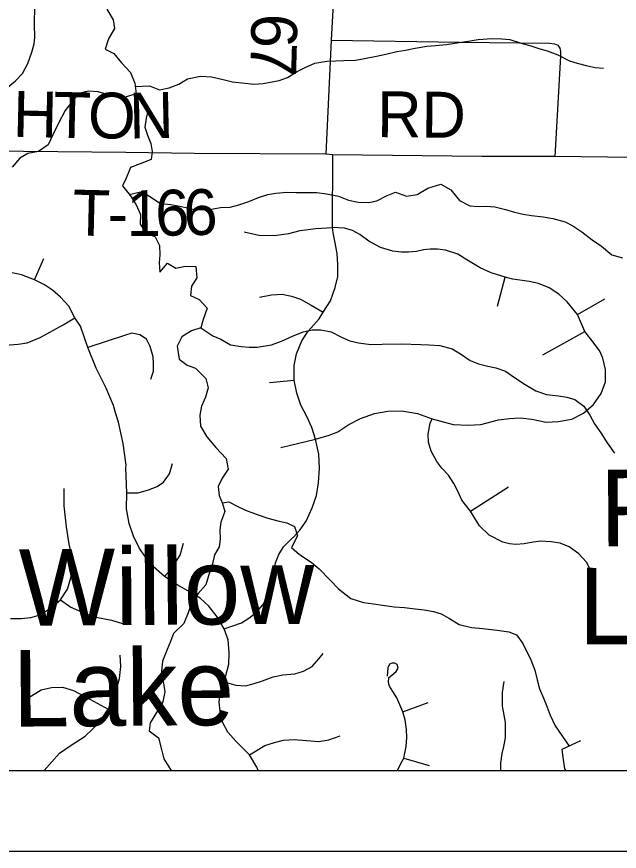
# Model space of a CAD drawing. Extents: x 0 to 34, y 0 to 22.
# Drawn here: x 3.245 to 3.992, y 14 to 15.034 of the extents above; entities that cross this region are included whole.
import ezdxf

# ---------------------------------------------------------------- set-up
doc = ezdxf.new("R2010")
doc.units = 0
for name, color, linetype in [('GM_X_County_Text', 7, 'Continuous'), ('GM_X_Minor_Lake', 7, 'Continuous'), ('GM_X_Minor_Lake_Text', 7, 'Continuous'), ('GM_X_Minor_River', 7, 'Continuous'), ('GM_X_Township_Road', 7, 'Continuous'), ('GM_X_Township_Road_Text', 7, 'Continuous'), ('SH_Cut_Line', 7, 'Continuous'), ('SH_Data', 7, 'Continuous')]:
    doc.layers.add(name, color=color, linetype=linetype)

msp = doc.modelspace()

# ---------------------------------------------------------------- linework, layer by layer
at = {"layer": 'GM_X_County_Text'}
msp.add_lwpolyline([(2.1, 15.3556), (2.1, 14.1), (4.3787, 14.1), (4.3725, 14.1373), (4.3676, 14.1533), (4.4185, 14.2906), (4.4707, 14.5032), (4.0058, 14.5086), (4.0092, 14.8604), (4.002, 15.1777), (4.1154, 15.1803), (4.1171, 15.3509), (3.8077, 15.3535), (3.6529, 15.3542), (3.32, 15.3518), (3.0143, 15.3554), (2.8413, 15.3568), (2.5967, 15.3568)], close=True, dxfattribs=at)
at = {"layer": 'GM_X_Minor_Lake'}
for points in [[(3.9435, 14.137), (3.9205, 14.1261)], [(3.9205, 14.1261), (3.9221, 14.1139), (3.9238, 14.1022), (3.9251, 14.1)]]:
    msp.add_lwpolyline(points, dxfattribs=at)
at = {"layer": 'GM_X_Minor_River'}
for points in [[(3.3566, 15.0437), (3.3644, 15.0305), (3.366, 15.0199), (3.3586, 15.0069), (3.3542, 14.9943), (3.3652, 14.9887), (3.3748, 14.9774), (3.3859, 14.9654), (3.391, 14.9522), (3.3927, 14.9389), (3.4022, 14.931), (3.408, 14.9208), (3.4051, 14.9086), (3.4034, 14.8976), (3.4069, 14.8878), (3.4108, 14.8772), (3.4128, 14.8673), (3.4114, 14.8574), (3.3978, 14.8519), (3.3857, 14.8476), (3.3802, 14.8343), (3.3757, 14.8247), (3.3857, 14.8123), (3.3927, 14.8013), (3.3981, 14.7892), (3.3979, 14.7771), (3.4052, 14.7665), (3.4162, 14.7617), (3.4216, 14.7508), (3.4222, 14.7394), (3.4211, 14.7295), (3.422, 14.7177), (3.4314, 14.7288), (3.442, 14.7229), (3.4534, 14.7253), (3.4667, 14.7247), (3.468, 14.7106), (3.4612, 14.7003), (3.4602, 14.6889), (3.4709, 14.6841), (3.4809, 14.6732), (3.4757, 14.659), (3.4728, 14.6487), (3.4615, 14.6452), (3.4494, 14.6375), (3.4435, 14.626), (3.4459, 14.6101), (3.4559, 14.6026), (3.4662, 14.5989), (3.4792, 14.5858), (3.482, 14.5744), (3.4787, 14.5629), (3.4739, 14.5519), (3.4717, 14.5405), (3.4723, 14.5268), (3.4804, 14.5136), (3.4915, 14.5004), (3.5042, 14.4869), (3.5066, 14.4736), (3.4995, 14.4625), (3.4943, 14.4522), (3.4956, 14.4412), (3.4998, 14.431), (3.5026, 14.4211), (3.4978, 14.4078), (3.4964, 14.3983), (3.4969, 14.3869), (3.4955, 14.3773), (3.4899, 14.3674), (3.487, 14.3545), (3.4826, 14.3415), (3.479, 14.3304)], [(3.3915, 14.948), (3.4092, 14.9486), (3.4218, 14.9438), (3.4335, 14.9462), (3.4456, 14.9509), (3.4565, 14.9575), (3.4724, 14.9607), (3.486, 14.9601), (3.5005, 14.9564), (3.5123, 14.9535), (3.5274, 14.9522), (3.5385, 14.9508), (3.5502, 14.9517), (3.5699, 14.9553), (3.5804, 14.9592), (3.5925, 14.9666), (3.6023, 14.9713), (3.6143, 14.9767), (3.6291, 14.9792), (3.6401, 14.9797), (3.6503, 14.9802), (3.6647, 14.9807), (3.6757, 14.9827), (3.6908, 14.9856), (3.7022, 14.988), (3.7158, 14.9912), (3.7264, 14.9928), (3.7385, 14.9956), (3.7528, 14.9981), (3.7638, 14.9989), (3.7774, 14.9998), (3.793, 15.0023), (3.8043, 15.0043), (3.8168, 15.006), (3.8335, 15.0073), (3.846, 15.0071), (3.8558, 15.0061), (3.8699, 15.0017), (3.8817, 14.9984), (3.892, 14.9951), (3.9022, 14.9921), (3.9152, 14.987), (3.9297, 14.9799), (3.9392, 14.977), (3.9506, 14.9741), (3.9616, 14.9715), (3.9718, 14.9705)], [(3.3927, 14.9389), (3.3791, 14.9346), (3.3662, 14.9363), (3.3555, 14.9385), (3.3456, 14.9414), (3.3335, 14.942), (3.3214, 14.9392), (3.3124, 14.9277), (3.3046, 14.9181), (3.296, 14.9017), (3.2894, 14.8879), (3.2838, 14.8757), (3.2718, 14.8672), (3.2586, 14.8648), (3.2488, 14.859), (3.239, 14.8479)], [(3.3842, 14.8142), (3.4001, 14.8178), (3.4096, 14.8114), (3.423, 14.8028), (3.4359, 14.8018), (3.4488, 14.7993), (3.4628, 14.7957), (3.4746, 14.7951), (3.486, 14.7959), (3.4973, 14.798), (3.5094, 14.7985), (3.52, 14.8013), (3.5325, 14.8052), (3.5442, 14.8103), (3.5559, 14.8142), (3.5657, 14.8158), (3.5793, 14.8171), (3.5911, 14.8165), (3.6036, 14.8166), (3.6165, 14.8164), (3.6286, 14.815), (3.6435, 14.8118), (3.656, 14.807), (3.6678, 14.8045), (3.6811, 14.8042), (3.6909, 14.8062), (3.7037, 14.8128), (3.7143, 14.8168), (3.728, 14.812), (3.7412, 14.814), (3.7544, 14.8221), (3.7703, 14.8269), (3.7828, 14.8198), (3.7936, 14.8066), (3.8062, 14.7999), (3.8168, 14.7993), (3.8267, 14.7994), (3.8373, 14.7988), (3.8506, 14.7955), (3.8616, 14.7922), (3.8722, 14.7897), (3.8829, 14.7879), (3.8973, 14.7865), (3.9091, 14.7844), (3.9243, 14.78), (3.9338, 14.7752), (3.9449, 14.7677), (3.9579, 14.758), (3.9693, 14.7501), (3.9823, 14.7392), (3.9956, 14.7356)], [(3.4728, 14.6487), (3.4877, 14.6387), (3.4976, 14.6346), (3.5098, 14.6279), (3.5235, 14.6258), (3.5329, 14.6247), (3.5428, 14.6248), (3.5606, 14.6277), (3.5727, 14.6324), (3.5866, 14.6383), (3.5998, 14.6437), (3.6108, 14.6465), (3.6218, 14.6463), (3.6343, 14.6437), (3.6473, 14.6374), (3.6576, 14.6326), (3.6682, 14.6301), (3.6834, 14.628), (3.6978, 14.6285), (3.7213, 14.6288), (3.7455, 14.6283), (3.7554, 14.6276), (3.769, 14.627), (3.7846, 14.6226), (3.7949, 14.6167), (3.8068, 14.6084), (3.8171, 14.604), (3.8288, 14.6011), (3.8387, 14.5993), (3.8505, 14.5949), (3.8616, 14.5874), (3.8749, 14.5784), (3.8879, 14.5706), (3.9012, 14.5662), (3.916, 14.5645), (3.9267, 14.5627), (3.9366, 14.5598), (3.9476, 14.5519), (3.955, 14.5406), (3.9608, 14.53), (3.9688, 14.5187), (3.9766, 14.5063), (3.9854, 14.4934)], [(3.4994, 14.432), (3.5078, 14.433), (3.5181, 14.4278), (3.5284, 14.4229), (3.5428, 14.4174), (3.5558, 14.413), (3.5698, 14.4093), (3.5793, 14.4072), (3.5888, 14.4027), (3.5928, 14.391), (3.5853, 14.3765), (3.5953, 14.3678), (3.6098, 14.3585), (3.6194, 14.3499), (3.6328, 14.3363), (3.6435, 14.3254), (3.6588, 14.3135), (3.6744, 14.3083), (3.6869, 14.3069), (3.6979, 14.3052), (3.7127, 14.3031), (3.7253, 14.3021), (3.7385, 14.3007), (3.7495, 14.2993), (3.7613, 14.2971), (3.7708, 14.2942), (3.7811, 14.2886), (3.793, 14.2812), (3.8082, 14.2772), (3.8184, 14.2765), (3.8294, 14.2755), (3.84, 14.2741), (3.8548, 14.272), (3.8643, 14.2683), (3.872, 14.2577), (3.8821, 14.2373), (3.8868, 14.2245), (3.8896, 14.2127), (3.8928, 14.2014), (3.8982, 14.1889), (3.9021, 14.1787), (3.906, 14.1688), (3.9122, 14.1556), (3.9292, 14.1302)], [(3.479, 14.3304), (3.4696, 14.3197), (3.4607, 14.3051), (3.4574, 14.2956), (3.4518, 14.2822), (3.4391, 14.2699), (3.4354, 14.26), (3.4313, 14.2501), (3.4254, 14.2356), (3.4241, 14.2227), (3.4257, 14.2132), (3.4281, 14.1976), (3.426, 14.1854), (3.4178, 14.1721), (3.41, 14.1591), (3.409, 14.1495), (3.4204, 14.1406), (3.424, 14.1262), (3.4272, 14.1148), (3.4353, 14.1012), (3.4361, 14.1)]]:
    msp.add_lwpolyline(points, dxfattribs=at)
at = {"layer": 'GM_X_Township_Road'}
for p, q in [((3.2668, 14.7085), (3.2784, 14.7348)), ((3.8404, 14.6757), (3.8499, 14.7114)), ((3.9398, 14.6655), (3.9736, 14.6848)), ((3.8969, 14.6154), (3.9489, 14.6442)), ((3.558, 14.5812), (3.5884, 14.5839)), ((3.572, 14.5004), (3.6149, 14.511)), ((3.8071, 14.4217), (3.8543, 14.4519)), ((3.7233, 14.173), (3.7546, 14.1844)), ((3.7244, 14.1153), (3.7559, 14.1062))]:
    msp.add_line(p, q, dxfattribs=at)
for points in [[(3.653, 15.3536), (3.6423, 15.1486), (3.6346, 15.0053), (3.628, 14.8639)], [(3.0894, 14.9172), (3.0915, 14.924), (3.1008, 14.9208), (3.1119, 14.9183), (3.1215, 14.9176), (3.1332, 14.9172), (3.1543, 14.9169), (3.165, 14.9172), (3.1849, 14.9215), (3.196, 14.9254), (3.2035, 14.9293), (3.2159, 14.9354), (3.2316, 14.9454), (3.2434, 14.955), (3.2519, 14.9639), (3.2584, 14.9764), (3.2633, 14.9903), (3.2662, 15.0006), (3.2673, 15.0088), (3.2669, 15.0252), (3.2673, 15.0473), (3.2673, 15.0719), (3.2673, 15.0858), (3.2675, 15.0945)], [(3.6346, 15.0053), (3.7936, 15.003), (3.905, 15.0018), (3.9114, 15.0009), (3.9153, 14.9991), (3.9178, 14.9956), (3.9187, 14.9915), (3.9187, 14.9857), (3.9115, 14.861)], [(4.0094, 14.8598), (3.9115, 14.861), (3.821, 14.8613), (3.6366, 14.8632), (3.628, 14.8639), (3.4647, 14.8648), (3.38, 14.8663), (3.1683, 14.8681), (3.1666, 14.8681), (3.0076, 14.867), (2.8745, 14.8645)], [(3.5869, 14.3888), (3.5876, 14.3895), (3.5956, 14.3979), (3.6035, 14.4093), (3.6107, 14.4256), (3.6161, 14.4411), (3.6187, 14.4567), (3.6199, 14.4749), (3.6191, 14.4924), (3.6149, 14.511), (3.6104, 14.5254), (3.6047, 14.5379), (3.5967, 14.5531), (3.5918, 14.5679), (3.5884, 14.5839), (3.5887, 14.6021), (3.5914, 14.6165), (3.5982, 14.6328), (3.6058, 14.6446), (3.6195, 14.6598), (3.6244, 14.6681), (3.6335, 14.6822), (3.6396, 14.6989), (3.6426, 14.7125), (3.6426, 14.7273), (3.6419, 14.741), (3.6388, 14.7562), (3.6369, 14.7664), (3.6362, 14.7732), (3.6366, 14.8632)], [(3.5265, 14.7679), (3.5447, 14.7638), (3.5637, 14.7634), (3.5819, 14.7657), (3.5959, 14.7694), (3.6153, 14.7721), (3.6362, 14.7732)], [(3.6149, 14.511), (3.632, 14.5159), (3.6426, 14.5201), (3.6563, 14.5288), (3.6707, 14.5364), (3.6882, 14.5425), (3.7045, 14.5455), (3.7216, 14.5459), (3.7413, 14.5425), (3.7595, 14.536), (3.7855, 14.5289), (3.8042, 14.5282), (3.8201, 14.5289), (3.842, 14.5347), (3.8556, 14.5364), (3.8688, 14.5372), (3.8833, 14.5356), (3.9011, 14.5318), (3.9159, 14.5326), (3.9326, 14.5356), (3.947, 14.5432), (3.9596, 14.5539), (3.969, 14.5675), (3.9744, 14.582), (3.9744, 14.5971), (3.9713, 14.6112), (3.9675, 14.6199), (3.9592, 14.6309), (3.9489, 14.6442), (3.9398, 14.6655), (3.9269, 14.681), (3.9167, 14.6905), (3.9045, 14.6985), (3.8916, 14.7038), (3.8799, 14.7064), (3.8681, 14.708), (3.8594, 14.7091), (3.8499, 14.7114), (3.8328, 14.7171), (3.8191, 14.7231), (3.8024, 14.733), (3.7914, 14.7402), (3.7763, 14.7449), (3.7663, 14.7465), (3.7572, 14.7465), (3.7489, 14.7456), (3.7403, 14.7436), (3.7303, 14.7425), (3.7216, 14.7427), (3.7109, 14.744), (3.6954, 14.7482), (3.681, 14.7562), (3.67, 14.7645), (3.6608, 14.7694), (3.651, 14.7725), (3.6362, 14.7732)], [(3.3677, 14.5423), (3.3646, 14.5527), (3.3556, 14.5739), (3.3431, 14.5989), (3.3329, 14.6245), (3.3239, 14.6508), (3.3169, 14.6614), (3.3092, 14.6755), (3.2989, 14.6867), (3.289, 14.6954), (3.279, 14.7021), (3.2668, 14.7085), (3.2505, 14.7146), (3.2393, 14.7168)], [(3.5458, 14.6867), (3.5603, 14.6897), (3.5736, 14.6905), (3.5853, 14.6882), (3.5963, 14.6844), (3.6096, 14.6768), (3.6244, 14.6681)], [(3.1537, 14.655), (3.1886, 14.6393), (3.2063, 14.6322), (3.2178, 14.629), (3.2306, 14.6274), (3.2466, 14.6287), (3.2575, 14.6303), (3.2736, 14.6367), (3.3021, 14.6527), (3.3169, 14.6614)], [(3.4111, 14.5851), (3.4143, 14.595), (3.4143, 14.6043), (3.414, 14.6127), (3.4101, 14.6258), (3.4057, 14.6348), (3.3973, 14.6402), (3.3874, 14.6421), (3.3797, 14.6399), (3.3329, 14.6245)], [(3.544, 14.1), (3.5424, 14.1041), (3.5333, 14.1197), (3.5162, 14.1364), (3.5064, 14.1477), (3.5003, 14.1591), (3.4973, 14.1698), (3.4957, 14.1849), (3.4969, 14.1959), (3.5018, 14.21), (3.5075, 14.232), (3.5079, 14.2464), (3.5068, 14.2621), (3.5018, 14.2757), (3.4932, 14.2905), (3.4829, 14.3039), (3.472, 14.3136), (3.4595, 14.3212), (3.4435, 14.3302), (3.4278, 14.3408), (3.4111, 14.3556), (3.3967, 14.3751), (3.3896, 14.3905), (3.3842, 14.4062), (3.3806, 14.4245), (3.381, 14.4444), (3.38, 14.4751), (3.3804, 14.4784), (3.3768, 14.5053), (3.3707, 14.5319), (3.3677, 14.5423)], [(3.9586, 14.3429), (3.9507, 14.3584), (3.9413, 14.3688), (3.9295, 14.3774), (3.9183, 14.3821), (3.9071, 14.3835), (3.8944, 14.3846), (3.8846, 14.3831), (3.8737, 14.3809), (3.8633, 14.3803), (3.8555, 14.3809), (3.8471, 14.3832), (3.8302, 14.3918), (3.8183, 14.4033), (3.8071, 14.4217), (3.7963, 14.4354), (3.7913, 14.4465), (3.7866, 14.4559), (3.7798, 14.4663), (3.7715, 14.4749), (3.7654, 14.4832), (3.7582, 14.4958), (3.755, 14.5073), (3.7546, 14.517), (3.7571, 14.5307), (3.7595, 14.536)], [(3.381, 14.4444), (3.3954, 14.4444), (3.4082, 14.4479), (3.4188, 14.452), (3.4265, 14.4575), (3.4339, 14.4678), (3.438, 14.4806)], [(3.237, 14.2886), (3.2502, 14.2886), (3.2624, 14.2898), (3.2736, 14.293), (3.2877, 14.3023), (3.2992, 14.3116), (3.3076, 14.3251), (3.312, 14.3389), (3.314, 14.3498), (3.314, 14.3629), (3.3098, 14.3806), (3.3063, 14.402), (3.3037, 14.428), (3.3037, 14.4498)], [(3.4278, 14.3408), (3.4374, 14.3514), (3.4473, 14.3671), (3.4515, 14.3818)], [(3.5018, 14.2757), (3.5235, 14.2832), (3.5326, 14.2889), (3.5424, 14.2969), (3.5496, 14.3053), (3.5553, 14.3151), (3.5599, 14.325), (3.5633, 14.3406), (3.5644, 14.3493), (3.5656, 14.3576), (3.5694, 14.3679), (3.5754, 14.3774), (3.5869, 14.3888)], [(3.2992, 14.3116), (3.312, 14.3027), (3.3306, 14.2943), (3.3431, 14.2902), (3.3624, 14.2866), (3.3787, 14.2815)], [(3.5018, 14.21), (3.5162, 14.2058), (3.5284, 14.2051), (3.5379, 14.2077), (3.5493, 14.2111), (3.5625, 14.2161), (3.5747, 14.2187), (3.5895, 14.2199), (3.6001, 14.2233), (3.6107, 14.229), (3.6191, 14.2385), (3.6244, 14.2453)], [(3.2788, 14.1), (3.2883, 14.111), (3.2979, 14.1215), (3.3111, 14.1308), (3.3294, 14.1427), (3.347, 14.1594), (3.3582, 14.176), (3.3656, 14.1901), (3.3723, 14.2142), (3.3739, 14.2292), (3.3731, 14.243)], [(3.7168, 14.1), (3.7204, 14.1079), (3.7244, 14.1153), (3.7275, 14.1301), (3.7282, 14.1409), (3.7278, 14.1508), (3.7261, 14.1631), (3.7233, 14.173), (3.7157, 14.1903), (3.7108, 14.198), (3.7068, 14.2045), (3.7054, 14.2094), (3.706, 14.2155), (3.7098, 14.2183), (3.7149, 14.2229), (3.7174, 14.2269), (3.7163, 14.2314), (3.7132, 14.2331), (3.71, 14.233), (3.7066, 14.232), (3.7047, 14.2275), (3.7039, 14.2172)], [(3.2598, 14.1905), (3.2752, 14.2001), (3.288, 14.203), (3.3015, 14.2033), (3.3152, 14.1994), (3.3354, 14.1885), (3.3582, 14.176)], [(3.8447, 14.1), (3.8447, 14.1092), (3.8464, 14.1214), (3.8486, 14.1298), (3.8506, 14.1405), (3.8506, 14.1498), (3.8506, 14.1596), (3.8487, 14.1686), (3.8468, 14.18), (3.8466, 14.1969), (3.8487, 14.2104)], [(3.5333, 14.1197), (3.5523, 14.131), (3.5641, 14.1348), (3.5754, 14.1379), (3.5887, 14.1386), (3.6039, 14.1375), (3.6187, 14.136), (3.6316, 14.1383), (3.6457, 14.1432)]]:
    msp.add_lwpolyline(points, dxfattribs=at)
at = {"layer": 'SH_Cut_Line'}
msp.add_lwpolyline([(2.1, 14.1), (8.9, 14.1)], dxfattribs=at)
at = {"layer": 'SH_Data'}
for p, q in [((2.1, 14.1), (8.9, 14.1)), ((2, 14), (9, 14))]:
    msp.add_line(p, q, dxfattribs=at)

# ---------------------------------------------------------------- texts
at = {"layer": 'GM_X_Minor_Lake_Text'}
for s, rotation, p in [('Fell', 0.4156, (3.9678, 14.378)), ('Willow ', 0.4161, (3.2478, 14.2794)), ('Lake', 359.9764, (3.941, 14.2566)), ('Lake', 0.4162, (3.2398, 14.1545))]:
    msp.add_text(s, height=0.09475, rotation=rotation, dxfattribs=at).set_placement(p)
at = {"layer": 'GM_X_Township_Road_Text'}
for s, height, rotation, p in [('6', 0.0568, 269.7138, (3.5355, 15.0382)), ('7', 0.0568, 268.3762, (3.5353, 15.0036)), ('H', 0.0568, 358.7177, (3.2396, 14.8857)), ('T', 0.0568, 358.7445, (3.2896, 14.8846)), ('O', 0.0568, 359.5495, (3.3329, 14.8837)), ('N', 0.0568, 1.1604, (3.3847, 14.8833)), ('RD', 0.05682, 359.5064, (3.6913, 14.8852)), ('T', 0.0568, 358.6585, (3.3134, 14.7634)), ('1', 0.0568, 0.5542, (3.3812, 14.7624)), ('6', 0.0568, 1.1248, (3.4169, 14.7627)), ('6', 0.0568, 1.2798, (3.452, 14.7634)), ('-', 0.0568, 359.9418, (3.3573, 14.7624))]:
    msp.add_text(s, height=height, rotation=rotation, dxfattribs=at).set_placement(p)

doc.saveas('drawing.dxf')
